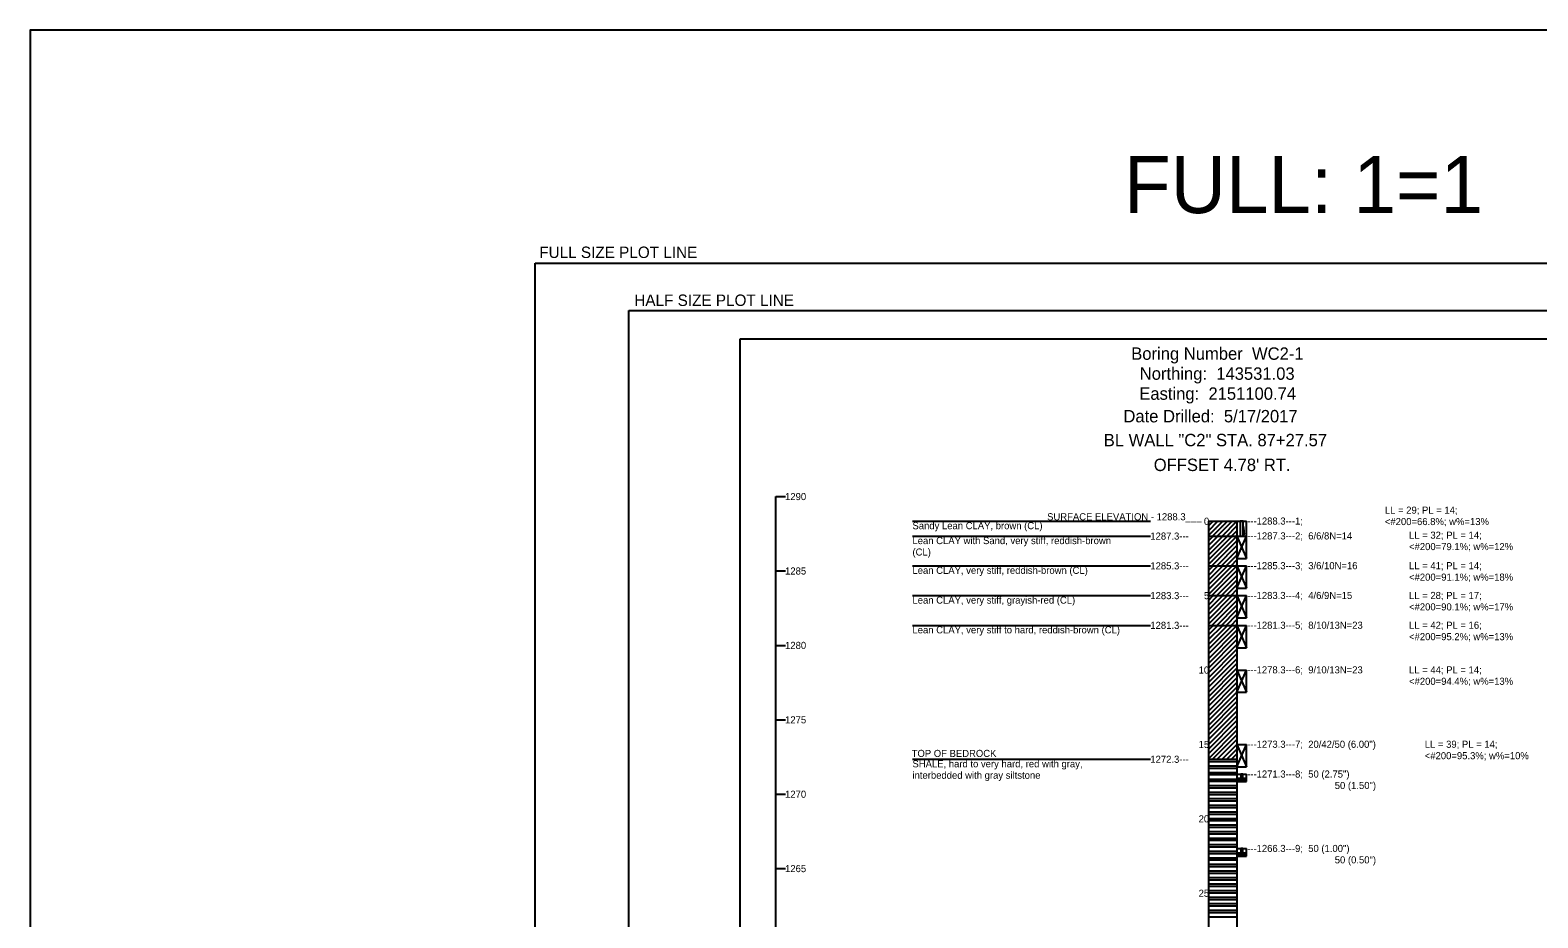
# Model space of a CAD drawing. Extents: x -2 to 138, y 24 to 58.
# Drawn here: x -2.21 to 24.17, y 42.52 to 58.05 of the extents above; entities that cross this region are included whole.
import ezdxf

# ---------------------------------------------------------------- set-up
doc = ezdxf.new("R2010")
doc.units = 0
for name, color, linetype in [('S', 7, 'Continuous'), ('SHT_Plot_Shape_Full', 7, 'Continuous'), ('SHT_Plot_Shape_Half', 7, 'Continuous'), ('SHT_Sheet_Border', 7, 'Continuous')]:
    doc.layers.add(name, color=color, linetype=linetype)

# ---------------------------------------------------------------- blocks, each defined once
blk = doc.blocks.new('POINT_DISPLAY')
blk.add_line((0, 0), (0, 0))

msp = doc.modelspace()

# ---------------------------------------------------------------- linework, layer by layer
msp.add_line((10.836, 36.866), (10.836, 49.887))
for points in [[(10.836, 49.887), (11.003, 49.887)], [(13.227, 49.456), (17.394, 49.456)], [(18.405, 49.373), (18.488, 49.456)], [(18.405, 49.29), (18.572, 49.456)], [(18.405, 49.206), (18.655, 49.456)], [(18.405, 49.456), (18.405, 37.217)], [(18.405, 49.456), (18.905, 49.456)], [(18.478, 49.196), (18.738, 49.456)], [(18.561, 49.196), (18.822, 49.456)], [(18.644, 49.196), (18.905, 49.456)], [(18.728, 49.196), (18.905, 49.373)], [(18.905, 49.456), (19.072, 49.456)], [(18.905, 49.456), (18.905, 37.217)], [(19.072, 49.196), (19.072, 49.456)], [(13.227, 49.196), (17.394, 49.196)], [(18.405, 49.196), (18.905, 49.196)], [(18.405, 49.113), (18.488, 49.196)], [(18.405, 49.029), (18.572, 49.196)], [(18.405, 48.946), (18.655, 49.196)], [(18.405, 48.863), (18.738, 49.196)], [(18.405, 48.779), (18.822, 49.196)], [(18.405, 48.696), (18.905, 49.196)], [(18.467, 48.675), (18.905, 49.113)], [(18.811, 49.196), (18.905, 49.29)], [(18.894, 49.196), (18.905, 49.206)], [(18.905, 49.196), (19.072, 49.196)], [(18.905, 49.196), (19.072, 48.805)], [(18.905, 48.805), (19.072, 49.196)], [(18.905, 49.196), (19.072, 49.196)], [(19.072, 48.805), (19.072, 49.196)], [(18.551, 48.675), (18.905, 49.029)], [(18.634, 48.675), (18.905, 48.946)], [(18.717, 48.675), (18.905, 48.863)], [(10.836, 48.585), (11.003, 48.585)], [(13.227, 48.675), (17.394, 48.675)], [(18.405, 48.675), (18.905, 48.675)], [(18.405, 48.592), (18.488, 48.675)], [(18.405, 48.509), (18.572, 48.675)], [(18.405, 48.425), (18.655, 48.675)], [(18.405, 48.342), (18.738, 48.675)], [(18.405, 48.259), (18.822, 48.675)], [(18.405, 48.175), (18.905, 48.675)], [(18.467, 48.154), (18.905, 48.592)], [(18.801, 48.675), (18.905, 48.779)], [(18.884, 48.675), (18.905, 48.696)], [(18.905, 48.805), (19.072, 48.805)], [(18.905, 48.675), (19.072, 48.285)], [(18.905, 48.285), (19.072, 48.675)], [(18.905, 48.675), (19.072, 48.675)], [(19.072, 48.285), (19.072, 48.675)], [(18.551, 48.154), (18.905, 48.509)], [(18.634, 48.154), (18.905, 48.425)], [(18.717, 48.154), (18.905, 48.342)], [(18.905, 48.285), (19.072, 48.285)], [(13.227, 48.154), (17.394, 48.154)], [(18.405, 48.154), (18.905, 48.154)], [(18.405, 48.071), (18.488, 48.154)], [(18.405, 47.988), (18.572, 48.154)], [(18.405, 47.904), (18.655, 48.154)], [(18.405, 47.821), (18.738, 48.154)], [(18.405, 47.738), (18.822, 48.154)], [(18.405, 47.654), (18.905, 48.154)], [(18.467, 47.634), (18.905, 48.071)], [(18.801, 48.154), (18.905, 48.259)], [(18.884, 48.154), (18.905, 48.175)], [(18.905, 48.154), (19.072, 47.764)], [(18.905, 47.764), (19.072, 48.154)], [(18.905, 48.154), (19.072, 48.154)], [(19.072, 47.764), (19.072, 48.154)], [(18.551, 47.634), (18.905, 47.988)], [(18.634, 47.634), (18.905, 47.904)], [(18.717, 47.634), (18.905, 47.821)], [(18.905, 47.764), (19.072, 47.764)], [(13.227, 47.634), (17.394, 47.634)], [(18.405, 47.634), (18.905, 47.634)], [(18.405, 47.55), (18.488, 47.634)], [(18.405, 47.467), (18.572, 47.634)], [(18.405, 47.384), (18.655, 47.634)], [(18.405, 47.3), (18.738, 47.634)], [(18.405, 47.217), (18.822, 47.634)], [(18.405, 47.134), (18.905, 47.634)], [(18.405, 47.05), (18.905, 47.55)], [(18.801, 47.634), (18.905, 47.738)], [(18.884, 47.634), (18.905, 47.654)], [(18.905, 47.634), (19.072, 47.243)], [(18.905, 47.243), (19.072, 47.634)], [(18.905, 47.634), (19.072, 47.634)], [(19.072, 47.243), (19.072, 47.634)], [(10.836, 47.283), (11.003, 47.283)], [(18.405, 46.967), (18.905, 47.467)], [(18.405, 46.884), (18.905, 47.384)], [(18.405, 46.8), (18.905, 47.3)], [(18.905, 47.243), (19.072, 47.243)], [(18.405, 46.717), (18.905, 47.217)], [(18.405, 46.634), (18.905, 47.134)], [(18.405, 46.55), (18.905, 47.05)], [(18.405, 46.467), (18.905, 46.967)], [(18.405, 46.384), (18.905, 46.884)], [(18.405, 46.3), (18.905, 46.8)], [(18.405, 46.217), (18.905, 46.717)], [(18.905, 46.852), (19.072, 46.462)], [(18.905, 46.462), (19.072, 46.852)], [(18.905, 46.852), (19.072, 46.852)], [(19.072, 46.462), (19.072, 46.852)], [(18.405, 46.134), (18.905, 46.634)], [(18.405, 46.05), (18.905, 46.55)], [(18.405, 45.967), (18.905, 46.467)], [(18.905, 46.462), (19.072, 46.462)], [(18.405, 45.884), (18.905, 46.384)], [(18.405, 45.8), (18.905, 46.3)], [(18.405, 45.717), (18.905, 46.217)], [(10.836, 45.981), (11.003, 45.981)], [(18.405, 45.634), (18.905, 46.134)], [(18.405, 45.55), (18.905, 46.05)], [(18.405, 45.467), (18.905, 45.967)], [(18.405, 45.384), (18.905, 45.884)], [(18.405, 45.3), (18.905, 45.8)], [(18.478, 45.29), (18.905, 45.717)], [(18.561, 45.29), (18.905, 45.634)], [(18.644, 45.29), (18.905, 45.55)], [(18.728, 45.29), (18.905, 45.467)], [(18.811, 45.29), (18.905, 45.384)], [(18.905, 45.55), (19.072, 45.16)], [(18.905, 45.16), (19.072, 45.55)], [(18.905, 45.55), (19.072, 45.55)], [(19.072, 45.16), (19.072, 45.55)], [(13.227, 45.29), (17.394, 45.29)], [(18.405, 45.29), (18.905, 45.29)], [(18.405, 45.29), (18.905, 45.29)], [(18.405, 45.25), (18.905, 45.25)], [(18.405, 45.175), (18.905, 45.175)], [(18.405, 45.136), (18.905, 45.136)], [(18.894, 45.29), (18.905, 45.3)], [(18.905, 45.16), (19.072, 45.16)], [(18.405, 45.06), (18.905, 45.06)], [(18.405, 45.021), (18.905, 45.021)], [(18.405, 44.945), (18.905, 44.945)], [(18.405, 44.906), (18.905, 44.906)], [(18.905, 45.029), (19.072, 45.029)], [(18.905, 44.899), (19.072, 44.899)], [(19.072, 44.899), (19.072, 45.029)], [(10.836, 44.679), (11.003, 44.679)], [(18.405, 44.83), (18.905, 44.83)], [(18.405, 44.791), (18.905, 44.791)], [(18.405, 44.716), (18.905, 44.716)], [(18.405, 44.676), (18.905, 44.676)], [(18.405, 44.601), (18.905, 44.601)], [(18.405, 44.561), (18.905, 44.561)], [(18.405, 44.486), (18.905, 44.486)], [(18.405, 44.447), (18.905, 44.447)], [(18.405, 44.371), (18.905, 44.371)], [(18.405, 44.332), (18.905, 44.332)], [(18.405, 44.256), (18.905, 44.256)], [(18.405, 44.217), (18.905, 44.217)], [(18.405, 44.141), (18.905, 44.141)], [(18.405, 44.102), (18.905, 44.102)], [(18.405, 44.027), (18.905, 44.027)], [(18.405, 43.987), (18.905, 43.987)], [(18.405, 43.912), (18.905, 43.912)], [(18.405, 43.872), (18.905, 43.872)], [(18.405, 43.797), (18.905, 43.797)], [(18.405, 43.758), (18.905, 43.758)], [(18.405, 43.682), (18.905, 43.682)], [(18.405, 43.643), (18.905, 43.643)], [(18.405, 43.567), (18.905, 43.567)], [(18.905, 43.727), (19.072, 43.727)], [(18.905, 43.597), (19.072, 43.597)], [(19.072, 43.597), (19.072, 43.727)], [(10.836, 43.377), (11.003, 43.377)], [(18.405, 43.528), (18.905, 43.528)], [(18.405, 43.452), (18.905, 43.452)], [(18.405, 43.413), (18.905, 43.413)], [(18.405, 43.338), (18.905, 43.338)], [(18.405, 43.298), (18.905, 43.298)], [(18.405, 43.223), (18.905, 43.223)], [(18.405, 43.183), (18.905, 43.183)], [(18.405, 43.108), (18.905, 43.108)], [(18.405, 43.069), (18.905, 43.069)], [(18.405, 42.993), (18.905, 42.993)], [(18.405, 42.954), (18.905, 42.954)], [(18.405, 42.878), (18.905, 42.878)], [(18.405, 42.839), (18.905, 42.839)], [(18.405, 42.764), (18.905, 42.764)], [(18.405, 42.724), (18.905, 42.724)], [(18.405, 42.649), (18.905, 42.649)], [(18.405, 42.609), (18.905, 42.609)], [(18.405, 42.534), (18.905, 42.534)]]:
    msp.add_lwpolyline(points)
for points in [[(18.963, 49.456), (18.963, 49.196), (19.013, 49.196), (19.013, 49.456)], [(19.028, 49.29), (19.022, 49.331), (19.013, 49.371), (19.028, 49.29)], [(19.013, 49.371), (19.013, 49.196), (19.028, 49.29), (19.013, 49.371)], [(19.013, 49.196), (19.03, 49.248), (19.028, 49.29), (19.013, 49.196)], [(19.013, 49.196), (19.028, 49.206), (19.03, 49.248), (19.013, 49.196)], [(19.013, 49.196), (19.026, 49.196), (19.028, 49.206), (19.013, 49.196)], [(18.972, 44.951), (18.905, 44.951), (18.988, 44.899), (18.972, 44.951)], [(18.972, 44.951), (19.005, 44.951), (19.005, 45.029), (18.972, 44.951)], [(18.972, 44.951), (19.005, 45.029), (18.972, 45.029), (18.972, 44.951)], [(18.972, 44.951), (18.988, 44.899), (19.005, 44.951), (18.972, 44.951)], [(18.988, 44.899), (19.072, 44.951), (19.005, 44.951), (18.988, 44.899)], [(18.972, 43.649), (18.905, 43.649), (18.988, 43.597), (18.972, 43.649)], [(18.972, 43.649), (19.005, 43.649), (19.005, 43.727), (18.972, 43.649)], [(18.972, 43.649), (19.005, 43.727), (18.972, 43.727), (18.972, 43.649)], [(18.972, 43.649), (18.988, 43.597), (19.005, 43.649), (18.972, 43.649)], [(18.988, 43.597), (19.072, 43.649), (19.005, 43.649), (18.988, 43.597)]]:
    msp.add_lwpolyline(points, close=True)
at = {"layer": 'S'}
msp.add_lwpolyline([(-2.212, 26.92), (137.529, 26.92), (137.529, 58.049), (-2.212, 58.049)], close=True, dxfattribs=at)
at = {"layer": 'SHT_Plot_Shape_Full'}
msp.add_lwpolyline([(6.624, 53.971), (42.624, 53.971), (42.624, 29.971), (6.624, 29.971)], close=True, dxfattribs=at)
at = {"layer": 'SHT_Plot_Shape_Half'}
msp.add_lwpolyline([(8.262, 53.146), (42.262, 53.146), (42.262, 31.146), (8.262, 31.146)], close=True, dxfattribs=at)
at = {"layer": 'SHT_Sheet_Border'}
msp.add_lwpolyline([(10.212, 52.646), (41.712, 52.646), (41.712, 31.646), (10.212, 31.646)], close=True, dxfattribs=at)

# ---------------------------------------------------------------- block references
at = {"xscale": 0.01, "yscale": 0.01}
for p in [(18.411, 49.373), (18.444, 49.44), (18.477, 49.34), (18.511, 49.406), (18.611, 49.44), (18.634, 49.376), (18.677, 49.34), (18.711, 49.406), (18.777, 49.34), (18.83, 49.423), (18.877, 49.373), (18.411, 49.113), (18.444, 49.273), (18.444, 49.179), (18.477, 49.206), (18.477, 49.079), (18.511, 49.146), (18.544, 49.306), (18.611, 49.24), (18.611, 49.179), (18.634, 49.116), (18.677, 49.079), (18.694, 49.264), (18.711, 49.206), (18.711, 49.146), (18.777, 49.079), (18.83, 49.163), (18.844, 49.273), (18.877, 49.113), (18.411, 48.879), (18.444, 49.013), (18.477, 48.946), (18.511, 48.846), (18.544, 49.046), (18.544, 48.913), (18.577, 48.813), (18.611, 48.979), (18.629, 48.902), (18.681, 48.832), (18.694, 49.004), (18.711, 48.946), (18.744, 48.846), (18.811, 48.813), (18.829, 48.928), (18.844, 49.013), (18.877, 48.879), (18.411, 48.679), (18.477, 48.746), (18.611, 48.713), (18.644, 48.779), (18.723, 48.746), (18.777, 48.679), (18.844, 48.746)]:
    msp.add_blockref('POINT_DISPLAY', p, dxfattribs=at)

# ---------------------------------------------------------------- texts
for s, height, p in [('Boring Number  WC2-1', 0.217, (17.055, 52.281)), ('Northing:  143531.03', 0.217, (17.204, 51.931)), ('Easting:  2151100.74', 0.217, (17.196, 51.581)), ('Date Drilled:  5/17/2017', 0.217, (16.918, 51.186)), ('BL WALL "C2" STA. 87+27.57', 0.217, (16.574, 50.768)), ("OFFSET 4.78' RT.", 0.217, (17.449, 50.334)), ('1290', 0.124, (10.998, 49.825)), ('SURFACE ELEVATION - 1288.3___', 0.124, (15.583, 49.472)), ('LL = 29; PL = 14;', 0.124, (21.493, 49.588)), ('Sandy Lean CLAY, brown (CL)', 0.124, (13.227, 49.316)), ('0', 0.124, (18.327, 49.394)), ('---1288.3---1;', 0.124, (19.083, 49.397)), ('<#200=66.8%; w%=13%', 0.124, (21.493, 49.388)), ('Lean CLAY with Sand, very stiff, reddish-brown', 0.124, (13.227, 49.055)), ('1287.3---', 0.124, (17.389, 49.134)), ('---1287.3---2;  6/6/8N=14', 0.124, (19.083, 49.137)), ('<#200=79.1%; w%=12%', 0.124, (21.916, 48.95)), ('LL = 32; PL = 14;', 0.124, (21.916, 49.15)), ('(CL)', 0.124, (13.227, 48.855)), ('1285', 0.124, (10.998, 48.523)), ('Lean CLAY, very stiff, reddish-brown (CL)', 0.124, (13.227, 48.535)), ('1285.3---', 0.124, (17.389, 48.613)), ('---1285.3---3;  3/6/10N=16', 0.124, (19.083, 48.616)), ('LL = 41; PL = 14;', 0.124, (21.916, 48.616)), ('<#200=91.1%; w%=18%', 0.124, (21.916, 48.416)), ('Lean CLAY, very stiff, grayish-red (CL)', 0.124, (13.227, 48.014)), ('1283.3---', 0.124, (17.389, 48.092)), ('5', 0.124, (18.327, 48.092)), ('---1283.3---4;  4/6/9N=15', 0.124, (19.083, 48.095)), ('<#200=90.1%; w%=17%', 0.124, (21.916, 47.895)), ('LL = 28; PL = 17;', 0.124, (21.916, 48.095)), ('Lean CLAY, very stiff to hard, reddish-brown (CL)', 0.124, (13.227, 47.493)), ('1281.3---', 0.124, (17.389, 47.572)), ('---1281.3---5;  8/10/13N=23', 0.124, (19.083, 47.574)), ('<#200=95.2%; w%=13%', 0.124, (21.916, 47.374)), ('LL = 42; PL = 16;', 0.124, (21.916, 47.574)), ('1280', 0.124, (10.998, 47.221)), ('10', 0.124, (18.234, 46.79)), ('---1278.3---6;  9/10/13N=23', 0.124, (19.083, 46.793)), ('<#200=94.4%; w%=13%', 0.124, (21.916, 46.593)), ('LL = 44; PL = 14;', 0.124, (21.916, 46.793)), ('1275', 0.124, (10.998, 45.919)), ('TOP OF BEDROCK', 0.124, (13.213, 45.331)), ('15', 0.124, (18.234, 45.488)), ('---1273.3---7;  20/42/50 (6.00")', 0.124, (19.083, 45.491)), ('<#200=95.3%; w%=10%', 0.124, (22.191, 45.291)), ('LL = 39; PL = 14;', 0.124, (22.191, 45.491)), ('SHALE, hard to very hard, red with gray,', 0.124, (13.227, 45.149)), ('1272.3---', 0.124, (17.389, 45.228)), ('interbedded with gray siltstone', 0.124, (13.227, 44.949)), ('---1271.3---8;  50 (2.75")', 0.124, (19.083, 44.97)), ('50 (1.50")', 0.124, (20.616, 44.77)), ('1270', 0.124, (10.998, 44.617)), ('20', 0.124, (18.234, 44.186)), ('---1266.3---9;  50 (1.00")', 0.124, (19.083, 43.668)), ('50 (0.50")', 0.124, (20.616, 43.468)), ('1265', 0.124, (10.998, 43.315)), ('25', 0.124, (18.234, 42.884))]:
    msp.add_text(s, height=height).set_placement(p)
at = {"layer": 'DEFPOINTS'}
for s, p in [('FULL SIZE PLOT LINE', (6.697, 54.062)), ('HALF SIZE PLOT LINE', (8.36, 53.223))]:
    msp.add_text(s, height=0.2, dxfattribs=at).set_placement(p)
at = {"layer": 'S'}
msp.add_text('FULL: 1=1   HALF: 1=2', height=1, dxfattribs=at).set_placement((16.93, 54.847))

doc.saveas('drawing.dxf')
